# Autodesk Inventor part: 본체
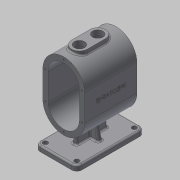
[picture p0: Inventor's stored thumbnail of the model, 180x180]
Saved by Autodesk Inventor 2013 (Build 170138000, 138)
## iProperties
Created: 2016-12
Part Number: 본체
Material: 일반
Document SubType Name: Modeling
Designer: mduedu
Density: 2.71 g/cm^3
Mass: 1171.02 g
Surface Area: 1014.94 cm^2
Volume: 432.112 cm^3
Author: mduedu
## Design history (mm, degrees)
sketch "스케치1"
  geometry: L1 (40, -25)-(40, 25); L2 (-40, 25)-(-40, -25); L3 (-40, -25)-(40, 25); L4 (40, -25)-(-40, 25); L5 (0, 25)-(0, -25); A1 r 40 centre (0, 25) between (40, 25) and (-40, 25); A2 r 40 centre (0, -25) between (-40, -25) and (40, -25); 1 further point
  constraints: 10 end point, 4 point on circle, 3 tangent, 2 centre point, 2 midpoint, 2 parallel, 1 vertical
  dimensions: "d0" = 130 dimension on A2 A1; "d2" = 80 distance between parallel lines of L1 L2
extrude "돌출1" new body sketch "스케치1" stored distance "d3" = 100; taper "d4" = 0 deg
feature "쉘1" dims "d5" = 10
sketch "스케치2"
  geometry: L1 (-90, 65)-(-100, 65); L2 (-100, 65)-(-100, -65); L3 (-100, -65)-(-90, -65); L4 (-90, -65)-(-90, 65); 2 further points
  constraints: 8 end point, 2 parallel, 1 horizontal, 1 horizontal alignment, 1 midpoint, 1 perpendicular
  dimensions: "d6" = 100 distance from line of L2 point (0, 0); "d7" = 130 distance of L1.end L2.end; "d8" = 10 distance of L2.end L3.end
extrude "돌출2" join sketch "스케치2" stored distance "d9" = 80; taper "d10" = 0 deg
fillet "모깎기1" dims "d11" = 10
sketch "스케치3"
  geometry: L1 (-10, 10)-(-10, 120) reference; L2 (60, 0)-(0, 0) reference; L3 (70, 120)-(70, 10) reference; L4 (0, 130)-(60, 130) reference; A1 r 10 centre (0, 120) between (0, 130) and (-10, 120) reference; A2 r 10 centre (0, 10) between (-10, 10) and (0, 0) reference; A3 r 10 centre (60, 10) between (60, 0) and (70, 10) reference; A4 r 10 centre (60, 120) between (70, 120) and (60, 130) reference; 5 further points
  constraints: 4 coincident
hole "구멍1" sketch "스케치3" at (60, 120), (60, 10), (0, 10), (0, 120) diameter "d12" = 9; stored, may be unused: countersink angle "d16" = 90 deg, drill point angle "d18" = 118 deg; dims "d13" = 6, "d14" = 4, "d15" = 2, "d17" = 8
sketch "스케치5"
  geometry: L1 (34, 35)-(26, 35); L2 (26, 35)-(26, 95); L3 (26, 95)-(34, 95); L4 (34, 95)-(34, 35); L5 (34, 35)-(26, 95); L6 (26, 35)-(34, 95); 1 further point
  constraints: 12 end point, 2 midpoint, 2 parallel, 1 horizontal, 1 perpendicular
  dimensions: "d22" = 8 distance of L2.end L3.end; "d24" = 60 distance of L1.end L2.end
extrude "돌출3" join sketch "스케치5" stored distance "d25" = 80; taper "d26" = 0 deg
feature "면 기울기1" dims angle "d27" = 5 deg
sketch "스케치6"
  geometry: L1 (-30, -90)-(30, -90) reference; L2 (-15.072, -62.052)-(-20, -90); A1 r 40 centre (0, -25) between (-40, -25) and (40, -25) reference; 1 further point
  constraints: 2 end point, 1 point on circle, 1 point on line
  dimensions: "d28" = 20 horizontal distance of A1.centre L2.end; "d29" = 80 deg angle of L2 L1
feature "리브1" sketch "스케치6" dims "d30" = 1, "d31" = 8, "d32" = 0, "d33" = 0, "d34" = 1, "d35" = 1
fillet "모깎기2" dims "d36" = 3
fillet "모깎기3" dims "d37" = 3, "d38" = 3
node "작업 평면1"
sketch "스케치9"
  geometry: 1 further point
sketch "스케치7"
  geometry: L1 (40, 50)-(-40, 50) reference; C1 r 15 at (0, 20); 1 further point
  constraints: 1 centre point, 1 vertical alignment
  dimensions: "d40" = 30 diameter of C1; "d41" = 30 distance from line of C1.centre L1
extrude "돌출4" join sketch "스케치7" stored distance "d42" = 80; taper "d43" = 0 deg
sketch "스케치15"
  geometry: C1 r 15 at (0, -15); C2 r 15 at (0, 20) reference; 1 further point
  constraints: 1 centre point, 1 vertical alignment
  dimensions: "d83" = 30 diameter of C1; "d84" = 35 distance of C1.centre C2.centre
extrude "돌출6" join sketch "스케치15" stored distance "d85" = 10; taper "d86" = 0 deg
hole "구멍2" diameter "d46" = 20; stored, may be unused: countersink angle "d50" = 90 deg, drill point angle "d52" = 118 deg; dims "d44" = 10, "d45" = 10, "d47" = 6, "d48" = 4, "d49" = 2, "d51" = 8
hole "구멍6" diameter "d89" = 20; stored, may be unused: countersink angle "d93" = 90 deg, drill point angle "d95" = 118 deg; dims "d87" = 10, "d88" = 10, "d90" = 6, "d91" = 4, "d92" = 2, "d94" = 8
node "작업 평면2"
sketch "스케치8"
  geometry: C1 r 15 at (0, 0) reference; C2 r 15 at (0, 0); 1 further point
  constraints: 1 centre point, 1 coincident
  dimensions: "d55" = 30 diameter of C2
extrude "돌출5" cut sketch "스케치8" stored distance "d56" = 80; taper "d57" = 0 deg
sketch "스케치16"
  geometry: C1 r 15 at (0, 35); 2 further points
  constraints: 1 centre point, 1 coincident, 1 vertical alignment
  dimensions: "d96" = 30 diameter of C1
extrude "돌출7" cut sketch "스케치16" stored distance "d97" = 10; taper "d98" = 0 deg
sketch "스케치17"
  geometry: L1 (15, 0)-(15, -35); L2 (-15, 0)-(-15, -35); C1 r 10 at (0, 0) reference; C2 r 10 at (0, -35) reference; A1 r 15 centre (0, 0) between (15, 0) and (-15, 0) reference; A2 r 15 centre (0, -35) between (15, -35) and (-15, -35) reference; 1 further point
  constraints: 4 end point, 4 point on circle, 3 tangent, 1 vertical
extrude "돌출8" join sketch "스케치17" stored distance "d99" = 10; taper "d100" = 0 deg
fillet "모깎기5" dims "d101" = 3
chamfer "모따기1" distance "d58" = 1; stored, may be unused: second distance "d59" = 2, angle "d60" = 45 deg
sketch "스케치10"
  geometry: 2 further points
  constraints: 1 coincident, 1 other
feature "엠보싱1" sketch "스케치10" dims "d0" = 130, "d2" = 80, "d11" = 10, "d61" = 0.5, "d62" = 0
sketch "스케치11"
  geometry: 1 further point
hole "구멍3" sketch "스케치11" at (0, 60) diameter "d63" = 3.242; stored, may be unused: countersink angle "d67" = 90 deg, drill point angle "d69" = 120 deg; dims "d64" = 8.6, "d65" = 4, "d66" = 2, "d68" = 10.6
sketch "스케치12"
  geometry: 1 further point
hole "구멍5" sketch "스케치12" at (0, 60) diameter "d70" = 3.242; stored, may be unused: countersink angle "d74" = 90 deg, drill point angle "d76" = 120 deg; dims "d71" = 8.6, "d72" = 4, "d73" = 2, "d75" = 10.6
node "솔리드1"
mirror "대칭1"
pattern_linear "직사각형 패턴1"
pattern_linear "직사각형 패턴2"
node "투영된 루프1"
sketch "스케치13"
  geometry: L1 (-40, 25)-(-40, -25) reference; L2 (40, -25)-(40, 25) reference; L3 (35, 25)-(35, -25); L4 (-35, -25)-(-35, 25); A1 r 40 centre (0, 25) between (40, 25) and (-40, 25) reference; A2 r 40 centre (0, -25) between (-40, -25) and (40, -25) reference; A3 r 35 centre (0, 25) between (35, 25) and (-35, 25); A4 r 35 centre (0, -25) between (-35, -25) and (35, -25); 2 further points
  constraints: 5 point on circle, 4 end point, 2 centre point, 3 other
  dimensions: "d77" = 5 distance between parallel lines of L3 L2
sketch "스케치14"
  geometry: L1 (-40, 25)-(-40, -25) reference; L2 (40, -25)-(40, 25) reference; L3 (35, 25)-(35, -25); L4 (-35, -25)-(-35, 25); A1 r 40 centre (0, 25) between (40, 25) and (-40, 25) reference; A2 r 40 centre (0, -25) between (-40, -25) and (40, -25) reference; A3 r 35 centre (0, 25) between (35, 25) and (-35, 25); A4 r 35 centre (0, -25) between (-35, -25) and (35, -25); 2 further points
  constraints: 5 point on circle, 4 end point, 2 centre point, 3 other
  dimensions: "d80" = 5 distance between parallel lines of L2 L3
node "투영된 루프3"
node "투영된 루프4"
node "투영된 루프5"
